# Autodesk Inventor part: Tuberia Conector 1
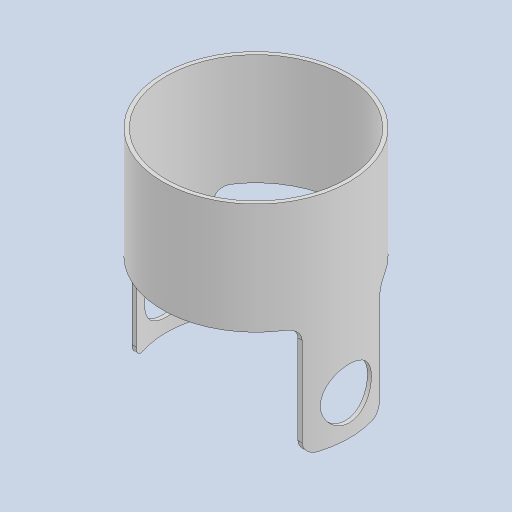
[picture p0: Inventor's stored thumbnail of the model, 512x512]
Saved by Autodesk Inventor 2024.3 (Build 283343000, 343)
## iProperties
Created: 2025-10
Part Number: Tuberia Conector 1
Material: Genérico
Document SubType Name: Modeling
Designer: Asus
Density: 1 g/cm^3
Appearance: Valor por defecto
Author: Asus
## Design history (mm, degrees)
sketch "Boceto1"
  geometry: C1 r 84.138 at (0, 0); C2 r 80.738 at (0, 0); 1 further point
  constraints: 2 centre point, 2 coincident
  dimensions: "d0" = 168.275 diameter of C1; "d1" = 3.4 radial gap between concentric circles of C1 C2
extrude "Extrusión1" new body sketch "Boceto1" distance "d2" = 200; taper "d3" = 0 deg
sketch "Boceto2"
  geometry: L1 (-200, -80.738)-(-200, 80.738) reference; L2 (-200, 84.138)-(-200, -84.138) reference; L3 (-100, 84.138)-(-100, 35); L4 (-100, 35)-(-200, 35); L5 (-200, -35)-(-100, -35); L6 (-100, -35)-(-100, -84.138); L7 (0, 84.138)-(-200, 84.138) reference; L8 (0, -84.138)-(-200, -84.138) reference; L9 (-240, 0)-(40, 0) reference; L10 (-100, 84.138)-(-200, 84.138); L11 (-200, 84.138)-(-200, 35); L12 (-200, 35)-(-100, 35); L13 (-100, 35)-(-100, 84.138); L14 (-200, -35)-(-100, -35); L15 (-100, -35)-(-100, -84.138); L16 (-100, -84.138)-(-200, -84.138); L17 (-200, -84.138)-(-200, -35); 3 further points
  constraints: 24 end point, 4 parallel, 3 perpendicular, 3 point on line, 2 horizontal, 2 midpoint, 1 vertical
  dimensions: "d4" = 70 distance between parallel lines of L5 L4; "d5" = 35 distance between parallel lines of L9 L4 (= 0.5 x d4); "d6" = 100 distance between parallel lines of L1 L6
extrude "Extrusión2" cut sketch "Boceto2" extent not by distance; stored distance "d7" = 0; taper "d8" = 0 deg
sketch "Boceto3"
  geometry: L1 (-240, 0)-(40, 0) reference; L2 (-200, -35)-(-200, 35) reference; 2 further points
  dimensions: "d9" = 0 distance from line of L1 point (-165, 0); "d10" = 35 distance from line of point (-165, 0) L2
hole "Agujero1" sketch "Boceto3" at (-165, 0) diameter "d11" = 46; stored, may be unused: countersink angle "d15" = 90 deg, drill point angle "d17" = 118 deg; dims "d12" = 6, "d13" = 4, "d14" = 2, "d16" = 8
fillet "Empalme1" dims "d18" = 10
node "Sólido1"
